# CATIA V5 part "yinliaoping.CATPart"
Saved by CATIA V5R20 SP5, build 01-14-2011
Part number: 饮料瓶
Material "Chessboard": density 2500 kg/m3
Bounding box of the stored display mesh (mm): x -25 to 25, y -25 to 25.2, z 0 to 110
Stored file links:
  E:\3.8  3D工程绘图\yinliaoping.CATPart
  C:\Program Files\Dassault Systemes\B20\intel_a\startup\materials\Catalog.CATMaterial
  C:\Program Files\Dassault Systemes\B20\intel_a\startup\materials\canvas.png
  C:\Program Files\Dassault Systemes\B20\intel_a\startup\materials\canvas.jpg
  C:\Program Files\Dassault Systemes\B20\intel_a\startup\materials\wall_of_bricks.jpg
  C:\Program Files\Dassault Systemes\B20\intel_a\startup\materials\DS_star.jpg
  C:\Program Files\Dassault Systemes\B20\intel_a\startup\materials\sunset.jpg
  C:\Program Files\Dassault Systemes\B20\intel_a\startup\materials\chessboard.jpg
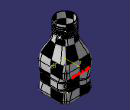
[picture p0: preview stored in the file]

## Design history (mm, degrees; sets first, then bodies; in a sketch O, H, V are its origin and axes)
Set1
  Sketch1 on xy-plane, origin (0, 0, 0), H (1, 0, 0), V (0, 1, 0)
    line L1 (25, 25) -> (25, -25)
    line L2 (25, -25) -> (-25, -25)
    line L3 (-25, -25) -> (-25, 25)
    line L4 (-25, 25) -> (25, 25)
    length L4 = 50
    length L1 = 50
    vertical: L1 V, L3 V
    horizontal: L2 H, L4 H
    equidistance: L1 L3 O, L2 L4 O
  Sketch2 on face of Pad1 from Sketch1.L4, origin (0, 25, 0), H (-1, 0, 0), V (0, 0, 1)
    spline S1 through (-33.4055, 12.6253) (-14.0192, 25.3939) (16.1326, 15.9014) (33.6444, 24.1329)
  Extrude1: Element1 Sketch2, Lim1 58, Lim2 58
  MultiSel1: CommonCtxFeats ({extract ExtractElem face of Pad1 from Sketch1.L4}; {extract ExtractElem face of Fillet1}; {extract ExtractElem face of Pad1 from Sketch1.L3}; {extract ExtractElem face of Fillet1}; {extract ExtractElem face of Pad1 from Sketch1.L2}; {extract ExtractElem face of Fillet1}; {extract ExtractElem face of Pad1 from Sketch1.L1}; {extract ExtractElem face of Fillet1})
  Sketch3 on face of Pad1 from Sketch1.L4, origin (0, 25, 0), H (-1, 0, 0), V (0, 0, 1)
    spline S1 through (-35.1975, 25.453) (-11.074, 35.1903) (7.2458, 28.1613) (33.3031, 32.9767)
  Extrude2: Element1 Sketch3, Lim1 68, Lim2 68
  MultiSel2: CommonCtxFeats ({extract ExtractElem face of Pad1 from Sketch1.L3}; {extract ExtractElem face of Fillet1}; {extract ExtractElem face of Pad1 from Sketch1.L2}; {extract ExtractElem face of Fillet1}; {extract ExtractElem face of Pad1 from Sketch1.L1}; {extract ExtractElem face of Fillet1}; {extract ExtractElem face of Pad1 from Sketch1.L4}; {extract ExtractElem face of Fillet1})
  Join1: Elements ({intersect ToIntersect1 {extract ExtractElem face of Pad1 from Sketch1.L4}, ToIntersect2 Extrude1}; {intersect ToIntersect1 {extract ExtractElem face of Fillet1}, ToIntersect2 Extrude1}; {intersect ToIntersect1 {extract ExtractElem face of Pad1 from Sketch1.L3}, ToIntersect2 Extrude1}; {intersect ToIntersect1 {extract ExtractElem face of Fillet1}, ToIntersect2 Extrude1}; {intersect ToIntersect1 {extract ExtractElem face of Pad1 from Sketch1.L2}, ToIntersect2 Extrude1}; {intersect ToIntersect1 {extract ExtractElem face of Fillet1}, ToIntersect2 Extrude1}; {intersect ToIntersect1 {extract ExtractElem face of Pad1 from Sketch1.L1}, ToIntersect2 Extrude1}; {intersect ToIntersect1 {extract ExtractElem face of Fillet1}, ToIntersect2 Extrude1})
  Join2: Elements ({intersect ToIntersect1 {extract ExtractElem face of Pad1 from Sketch1.L3}, ToIntersect2 Extrude2}; {intersect ToIntersect1 {extract ExtractElem face of Fillet1}, ToIntersect2 Extrude2}; {intersect ToIntersect1 {extract ExtractElem face of Pad1 from Sketch1.L2}, ToIntersect2 Extrude2}; {intersect ToIntersect1 {extract ExtractElem face of Fillet1}, ToIntersect2 Extrude2}; {intersect ToIntersect1 {extract ExtractElem face of Pad1 from Sketch1.L1}, ToIntersect2 Extrude2}; {intersect ToIntersect1 {extract ExtractElem face of Fillet1}, ToIntersect2 Extrude2}; {intersect ToIntersect1 {extract ExtractElem face of Pad1 from Sketch1.L4}, ToIntersect2 Extrude2}; {intersect ToIntersect1 {extract ExtractElem face of Fillet1}, ToIntersect2 Extrude2})
  Plane1: type Normal, Curve Join2, RefPoint vertex [face of MultiSel2 | face of MultiSel2]
  Plane2: type Normal, Curve Join1, RefPoint vertex [face of MultiSel1 | face of MultiSel1]
  Circle1: type CtrRad, Start 0, End 180, Center vertex [face of MultiSel2 | face of MultiSel2], Support Plane1, Radius 1, FirstDirection (0, 1, 0)
  Circle2: type CtrRad, Start 0, End 180, Center vertex [face of MultiSel1 | face of MultiSel1], Support Plane2, Radius 1, FirstDirection (0, 1, 0)
Body1 (main body), material "Chessboard"
  Pad1: profile Sketch1, direction (0, 0, 1), length 50
  Fillet1: on edge [face of Pad1 from Sketch1.L4 | face of Pad1 from Sketch1.L1]; edge [face of Pad1 from Sketch1.L3 | face of Pad1 from Sketch1.L4]; edge [face of Pad1 from Sketch1.L1 | face of Pad1 from Sketch1.L2]; edge [face of Pad1 from Sketch1.L2 | face of Pad1 from Sketch1.L3]
  Fillet2: radius 8, on edge [start face of Pad1 | face of Fillet1]
  Plane3: type Offset, RefPlane xy-plane, Offset 90
  Sketch4 on Plane3, origin (0, 0, 90), H (1, 0, 0), V (0, 1, 0)
    circle A1 centre (0, 0) radius 15
    radius A1 = 15
  Pad2: profile Sketch4, direction (0, 0, 1), length 20
  Sketch5 on end face of Pad1, origin (0, 0, 50), H (1, 0, 0), V (0, 1, 0)
    point P1 (25, 0)
    distance P1 O = 25
    coincidence: P1 H
  Sketch6 on start face of Pad2, origin (0, 0, 90), H (1, 0, 0), V (0, -1, 0)
    point P1 (15, 0)
    distance P1 O = 15
    coincidence: P1 H
  Loft1: solid, Sections ({boundary Boundary {extract ExtractElem end face of Pad1}}; {boundary Boundary {extract ExtractElem start face of Pad2}}), StartFace end face of Pad1, EndFace start face of Pad2
  Slot1: profile Circle1, centre curve Join2
  Slot2: profile Circle2, centre curve Join1
  Shell1: ExtOffset 0, Face end face of Pad2, IntOffset 1
  Sketch7 on Plane3, origin (0, 0, 90), H (1, 0, 0), V (0, 1, 0)
    point P1 (15, 0)
    distance P1 O = 15
    coincidence: P1 H
  Helix1: Direction Z axis, RefPoint Sketch7, Pitch 3, Height 18, TaperAngle 0
  Point1: type OnCurve, Support Helix1, RefPoint vertex of Helix1, Length -5
  Point2: type OnCurve, Support Helix1, Length 5
  Line1: type PtDir, RefPoint vertex of Helix1, Direction (1, 0, 0), Start 0, End 10
  Line2: type PtDir, RefPoint Sketch6, Direction (1, 0, 0), Start 0, End 10
  Connect1: Curve1 Line1, Point1 vertex of Line1, Tension1 1, Curve2 Helix1, Point2 Point1, Tension2 1
  Connect2: Curve1 Line2, Point1 vertex of Line2, Tension1 1, Curve2 Connect1, Point2 Point2, Tension2 1
  Plane4: type Normal, Curve Connect2, RefPoint Point2
  Sketch8 on Plane4, origin (-0.9376, 2.7093, 0.0913), H (-0.945, -0.327, 0), V (0.0104, -0.0301, 0.9995)
    circle A1 centre (-14.8219, 89.8123) radius 1
    radius A1 = 1
  Rib1: profile Sketch8, centre curve Connect2
  Body2
    Sketch9 on Plane3, origin (0, 0, 90), H (1, 0, 0), V (0, 1, 0)
      circle A1 centre (0, 0) radius 14
      radius A1 = 14
    Pad3: profile Sketch9, direction (0, 0, 1), length 40, mirrored extent
  Remove1: tool Body2
Body3
  Sketch10 on face of Pad1 from Sketch1.L4, origin (0, 25, 0), H (-1, 0, 0), V (0, 0, 1)
    polyline C1
    polyline C2
    polyline C3
    polyline C4
    polyline C5
    polyline C6
    polyline C7
    polyline C8
    polyline C9
    polyline C10
    polyline C11
  Pad4: profile Sketch10, direction (0, 1, 0), length 0.2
